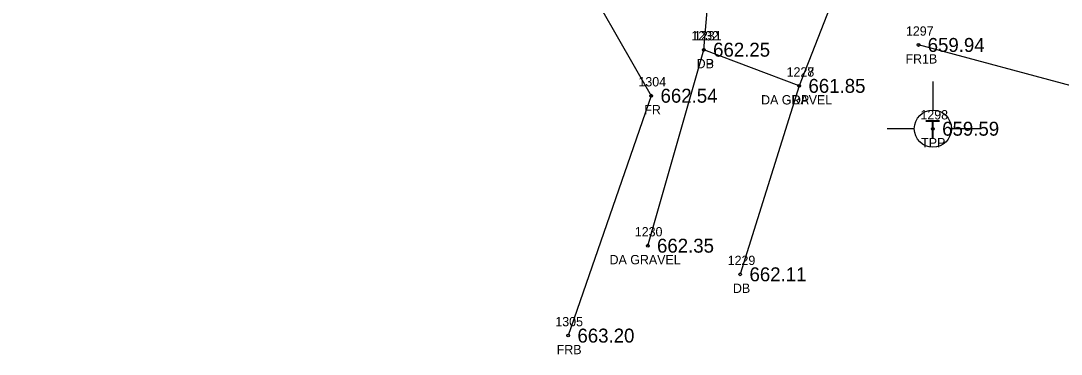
# Model space of a CAD drawing. Extents: x 1655137 to 1657928, y 1003994 to 1005407.
# Drawn here: x 1656148.5 to 1656260.6, y 1004609.3 to 1004645.1 of the extents above; entities that cross this region are included whole.
import ezdxf

# ---------------------------------------------------------------- set-up
doc = ezdxf.new("R2010")
doc.units = 0
for name, color, linetype in [('RD_EX_Driveway', 7, 'Continuous'), ('RD_EX_Driveway_txCode', 7, 'Continuous'), ('RD_EX_Fence_Other', 7, 'Continuous'), ('RD_EX_Fence_Other_txCode', 7, 'Continuous'), ('RD_EX_TX_Driveway_ELEV', 7, 'Continuous'), ('RD_EX_TX_Fence_Other_ELEV', 7, 'Continuous'), ('RD_EX_TX_UT_ELEV', 7, 'Continuous'), ('RD_EX_UT', 7, 'Continuous'), ('RD_EX_UT_txCode', 7, 'Continuous'), ('RD_SMD_Locator', 7, 'Continuous')]:
    doc.layers.add(name, color=color, linetype=linetype)

msp = doc.modelspace()

# ---------------------------------------------------------------- linework, layer by layer
at = {"layer": 'RD_EX_Driveway'}
for p, q in [((1656216.06, 1004620.95), (1656222.1, 1004642.03)), ((1656232.37, 1004638.14), (1656226.02, 1004617.87))]:
    msp.add_line(p, q, dxfattribs=at)
msp.add_lwpolyline([(1656244.5, 1004656.52), (1656239.14, 1004653.11), (1656236.39, 1004648.45), (1656232.37, 1004638.14), (1656222.1, 1004642.03), (1656223.04, 1004653), (1656223.47, 1004658.05), (1656222.03, 1004663.57)], dxfattribs=at)
at = {"layer": 'RD_EX_Fence_Other'}
msp.add_line((1656275.88, 1004634.36), (1656245.21, 1004642.54), dxfattribs=at)
msp.add_lwpolyline([(1656052.39, 1004677.71), (1656061.84, 1004701.05), (1656117.12, 1004682.78), (1656207.41, 1004652.79), (1656216.44, 1004637.08), (1656207.49, 1004611.28)], dxfattribs=at)
at = {"layer": 'RD_EX_UT'}
for p, q in [((1656246.77, 1004638.6), (1656246.77, 1004635.53)), ((1656241.84, 1004633.54), (1656244.77, 1004633.54)), ((1656248.77, 1004633.54), (1656251.84, 1004633.54))]:
    msp.add_line(p, q, dxfattribs=at)
msp.add_circle((1656246.77, 1004633.53), 2, dxfattribs=at)
at = {"layer": 'RD_SMD_Locator'}
for centre in [(1656222.1, 1004642.03), (1656222.1, 1004642.03), (1656245.21, 1004642.54), (1656232.37, 1004638.14), (1656232.37, 1004638.14), (1656216.44, 1004637.08), (1656246.77, 1004633.53), (1656216.06, 1004620.95), (1656226.02, 1004617.87), (1656207.49, 1004611.28)]:
    msp.add_circle(centre, 0.15, dxfattribs=at)

# ---------------------------------------------------------------- texts
at = {"layer": 'RD_EX_Driveway_txCode'}
for s, p in [('1232', (1656220.76, 1004643.03)), ('1231', (1656221.04, 1004643.03)), ('DB', (1656221.33, 1004640.03)), ('DP', (1656221.33, 1004640.03)), ('1227', (1656231.02, 1004639.14)), ('1228', (1656231.02, 1004639.14)), ('DA GRAVEL', (1656228.27, 1004636.14)), ('DP', (1656231.59, 1004636.14)), ('1230', (1656214.67, 1004621.95)), ('DA GRAVEL', (1656211.95, 1004618.95)), ('1229', (1656224.67, 1004618.87)), ('DB', (1656225.24, 1004615.87))]:
    msp.add_text(s, height=1, dxfattribs=at).set_placement(p)
at = {"layer": 'RD_EX_Fence_Other_txCode'}
for s, p in [('1297', (1656243.87, 1004643.54)), ('FR1B', (1656243.82, 1004640.54)), ('1304', (1656215.06, 1004638.08)), ('FR', (1656215.69, 1004635.08)), ('1305', (1656206.11, 1004612.28)), ('FRB', (1656206.26, 1004609.28))]:
    msp.add_text(s, height=1, dxfattribs=at).set_placement(p)
at = {"layer": 'RD_EX_TX_Driveway_ELEV'}
for s, p in [('662.25', (1656223.1, 1004641.28)), ('662.25', (1656223.1, 1004641.28)), ('661.85', (1656233.37, 1004637.39)), ('661.85', (1656233.37, 1004637.39)), ('662.35', (1656217.06, 1004620.2)), ('662.11', (1656227.02, 1004617.12))]:
    msp.add_text(s, height=1.5, dxfattribs=at).set_placement(p)
at = {"layer": 'RD_EX_TX_Fence_Other_ELEV'}
for s, p in [('659.94', (1656246.21, 1004641.79)), ('662.54', (1656217.44, 1004636.33)), ('663.20', (1656208.49, 1004610.53))]:
    msp.add_text(s, height=1.5, dxfattribs=at).set_placement(p)
at = {"layer": 'RD_EX_TX_UT_ELEV'}
msp.add_text('659.59', height=1.5, dxfattribs=at).set_placement((1656247.77, 1004632.78))
at = {"layer": 'RD_EX_UT'}
msp.add_text('T', height=2, dxfattribs=at).set_placement((1656245.93, 1004632.48))
at = {"layer": 'RD_EX_UT_txCode'}
for s, p in [('1298', (1656245.43, 1004634.53)), ('TPP', (1656245.51, 1004631.53))]:
    msp.add_text(s, height=1, dxfattribs=at).set_placement(p)

doc.saveas('drawing.dxf')
